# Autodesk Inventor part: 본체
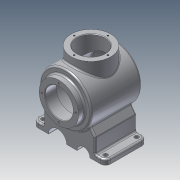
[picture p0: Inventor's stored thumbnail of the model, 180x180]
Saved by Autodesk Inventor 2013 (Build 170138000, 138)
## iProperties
Created: 2018-08
Part Number: 본체
Material: 알루미늄 6061
Document SubType Name: Modeling
Designer: Administrator
Mass: 1886 g
Surface Area: 1087.42 cm^2
Volume: 695.939 cm^3
Density: 2.71 g/cm^3
Author: Administrator
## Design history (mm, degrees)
sketch "스케치1"
  geometry: L1 (0, 0)-(0, 50); L2 (0, 50)-(96.671, 50); L3 (0, 0)-(108, 0); A1 r 116 centre (-8, 0) between (108, 0) and (96.671, 50); 1 further point
  constraints: 6 end point, 2 coincident, 2 horizontal alignment, 2 point on circle, 1 centre point, 1 parallel, 1 perpendicular, 1 vertical
  dimensions: "d0" = 50 distance of L1.start L1.end; "d2" = 108 distance of L3.end L1.start; "d3" = 116 radius of A1
revolve "회전1" sketch "스케치1" stored, may be unused: angle "d4" = 90 deg
feature "쉘1" dims "d5" = 10
node "작업 평면1"
sketch "스케치2"
  geometry: C1 r 38 at (0, 0); 1 further point
  constraints: 1 centre point, 1 coincident
  dimensions: "d7" = 76 diameter of C1
extrude "돌출1" join sketch "스케치2" stored distance "d8" = 10; taper "d9" = 0 deg
sketch "스케치3"
  geometry: C1 r 38 at (0, 0) reference; C2 r 27 at (0, 0)
  constraints: 1 centre point, 1 coincident
  dimensions: "d10" = 54 diameter of C2
extrude "돌출2" cut sketch "스케치3" stored distance "d11" = 10; taper "d12" = 0 deg
node "작업 평면2"
sketch "스케치4"
  geometry: L1 (-96.671, 50)-(-96.671, -50) reference; L2 (0, 50)-(0, -50) reference; L3 (0, -50)-(-96.671, -50) reference; C1 r 38 at (-50, 0); 3 further points
  constraints: 2 midpoint, 1 centre point, 1 horizontal alignment
  dimensions: "d14" = 76 diameter of C1; "d79" = 50 distance from line of L2 C1.centre
extrude "돌출3" join sketch "스케치4" stored distance "d15" = 10; taper "d16" = 0 deg
node "작업 평면3"
sketch "스케치5"
  geometry: L1 (82, 70)-(72, 70); L2 (72, 70)-(72, 50); L3 (82, 70)-(82, -70); L4 (82, -70)-(72, -70); L5 (72, -70)-(72, -50); L6 (72, -70)-(29.59, -40.304); L7 (72, -70)-(123.773, -70); L8 (72, 70)-(29.59, 40.304); L9 (72, 70)-(123.773, 70); L10 (72, 50)-(43.437, 50); L11 (72, -50)-(43.437, -50); A1 r 50 centre (0, 0) between (29.59, -40.304) and (29.59, 40.304) reference; 2 further points
  constraints: 22 end point, 3 horizontal, 3 perpendicular, 2 equal length, 2 parallel, 2 point on circle, 2 point on line, 1 horizontal alignment, 1 midpoint
  dimensions: "d18" = 10 distance between parallel lines of L2 L3; "d20" = 140 distance of L1.start L3.end; "d21" = 10 distance between parallel lines of L3 L5; "d22" = 20 distance of L4.end L5.end; "d23" = 20 distance of L1.end L2.end; "d25" = 82 distance of point (0, 0) point (82, 0); "d26" = 145 deg angle of L7 L6; "d28" = 145 deg angle of L8 L9
extrude "돌출4" join sketch "스케치5" distance "d29" = 80; taper "d30" = 0 deg
sketch "스케치6"
  geometry: L1 (-70, -82)-(70, -82) reference; C1 r 12.5 at (-27.5, -82); C2 r 17.5 at (22.5, -82); A1 r 50 centre (0, 0) between (-40.304, -29.59) and (40.304, -29.59) reference
  constraints: 2 centre point, 2 point on line
  dimensions: "d31" = 25 diameter of C1; "d32" = 35 diameter of C2; "d33" = 27.5 horizontal distance of A1.centre C1.centre; "d34" = 22.5 horizontal distance of A1.centre C2.centre
extrude "돌출5" cut sketch "스케치6" stored distance "d35" = 80; taper "d36" = 0 deg
sketch "스케치7"
  geometry: C1 r 27 at (0, 0) reference; 1 further point
  constraints: 1 vertical alignment
  dimensions: "d37" = 32.5 distance of point (0, 32.5) C1.centre
hole "구멍1" sketch "스케치7" at (0, 32.5) diameter "d38" = 3.242; stored, may be unused: countersink angle "d42" = 90 deg, drill point angle "d44" = 118 deg; dims "d39" = 8, "d40" = 4, "d41" = 2, "d43" = 10
sketch "스케치8"
  geometry: C1 r 38 at (0, 0) reference; C2 r 27 at (0, 0); 1 further point
  constraints: 1 centre point, 1 coincident
  dimensions: "d48" = 54 diameter of C2
extrude "돌출6" cut sketch "스케치8" stored distance "d49" = 80; taper "d50" = 0 deg
sketch "스케치9"
  geometry: C1 r 27 at (0, 0) reference; 2 further points
  constraints: 1 vertical alignment
  dimensions: "d51" = 32.5 distance of point (0, 32.5) C1.centre
hole "구멍2" sketch "스케치9" at (0, 32.5) diameter "d52" = 3.242; stored, may be unused: countersink angle "d56" = 90 deg, drill point angle "d58" = 118 deg; dims "d53" = 8, "d54" = 4, "d55" = 2, "d57" = 10
fillet "모깎기1" dims "d62" = 10
sketch "스케치10"
  geometry: C1 r 4 at (70, -10); C2 r 4 at (10, -10); A1 r 10 centre (70, -10) between (70, -20) and (80, -10) reference; A2 r 10 centre (10, -10) between (0, -10) and (10, -20) reference; 1 further point
  constraints: 2 centre point, 2 coincident
  dimensions: "d63" = 8 diameter of C1; "d64" = 8 diameter of C2
extrude "돌출7" cut sketch "스케치10" stored distance "d65" = 80; taper "d66" = 0 deg
chamfer "모따기1" distance "d67" = 1; stored, may be unused: second distance "d68" = 2, angle "d69" = 45 deg
fillet "모깎기2" dims "d70" = 3
fillet "모깎기3" dims "d71" = 3
fillet "모깎기4" dims "d72" = 3
fillet "모깎기5" dims "d73" = 3
fillet "모깎기6" dims "d74" = 3
node "작업 평면4"
sketch "스케치11"
  geometry: C1 r 32.5 at (0, 0); 1 further point
  constraints: 1 centre point, 1 coincident, 1 other
  dimensions: "d76" = 65 diameter of C1
feature "엠보싱1" sketch "스케치11" dims "d12" = 0, "d77" = 0.5, "d78" = 0
node "솔리드1"
pattern_circular "원형 패턴1" dims angle "d46" = 360 deg
pattern_circular "원형 패턴2" dims angle "d60" = 360 deg
mirror "대칭1"
other parameters: "d6" = 12, "d13" = 65, "d17" = 8
